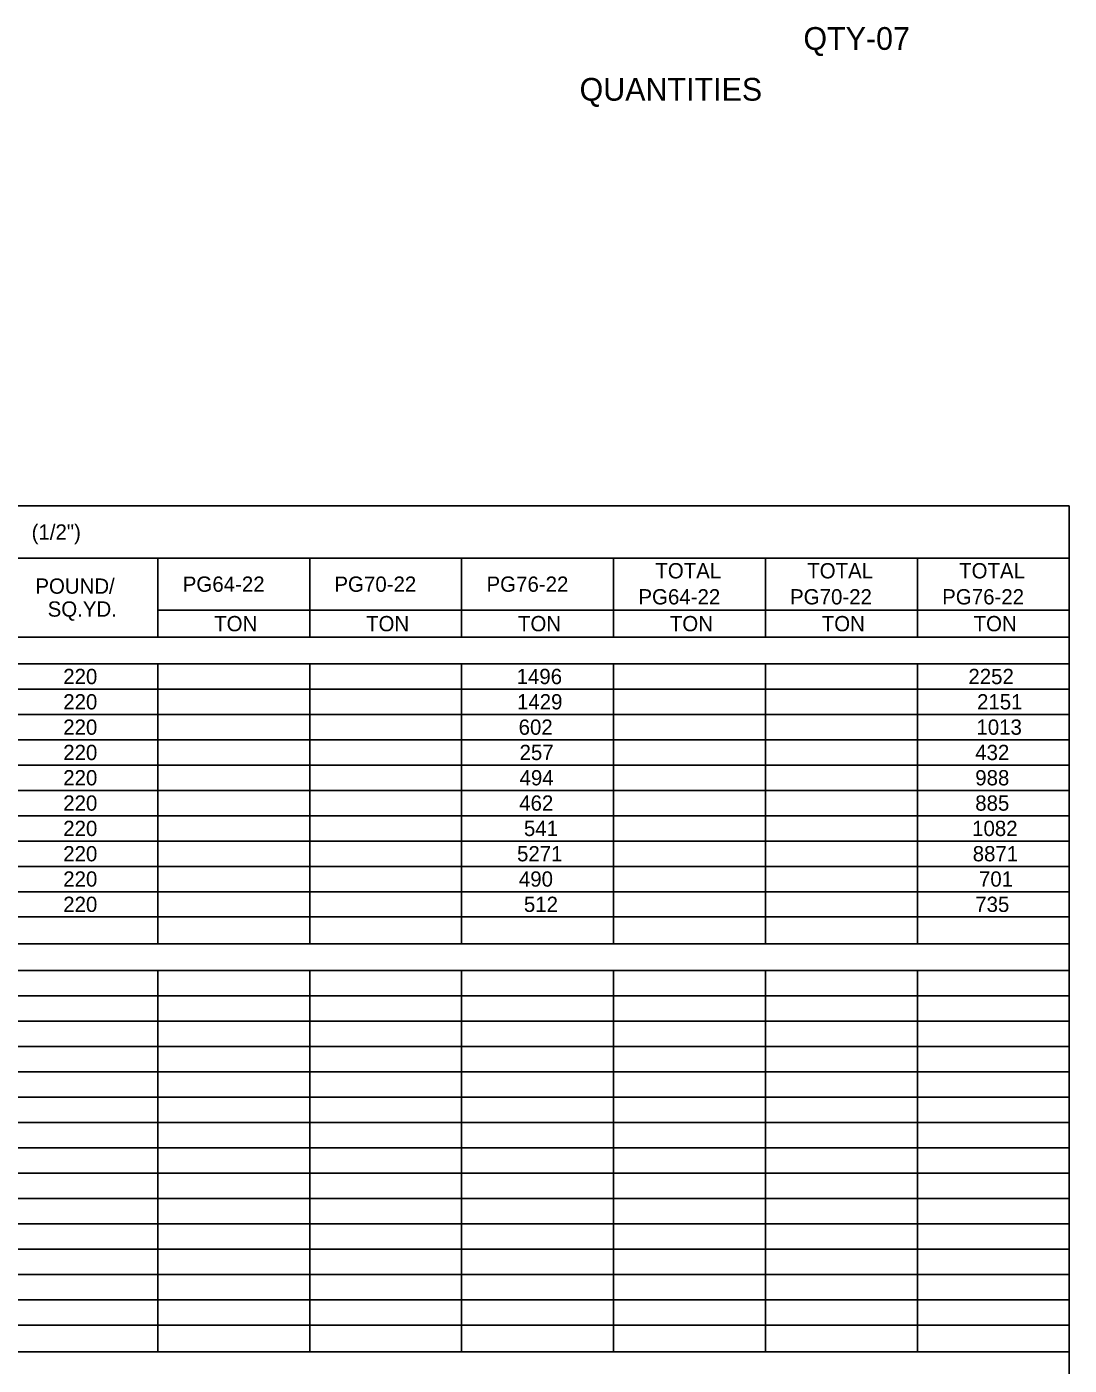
# Model space of a CAD drawing. Extents: x 1226590 to 1228573, y 151304 to 154224.
# Drawn here: x 1227882.1 to 1228150.7, y 151960.6 to 152305.5 of the extents above; entities that cross this region are included whole.
import ezdxf

# ---------------------------------------------------------------- set-up
doc = ezdxf.new("R2010")
doc.units = 0
doc.layers.add('R_Border', color=7, linetype='Continuous')
doc.layers.add('R_Dimension', color=7, linetype='Continuous')

msp = doc.modelspace()

# ---------------------------------------------------------------- linework, layer by layer
at = {"layer": 'R_Dimension'}
for p, q in [((1226590.27, 152182.03), (1228150.73, 152182.03)), ((1228150.73, 151484.92), (1228150.73, 152182.03)), ((1226898.37, 152168.6), (1228150.73, 152168.6)), ((1227915.91, 152148.27), (1227915.91, 152168.6)), ((1227955.05, 152148.27), (1227955.05, 152168.6)), ((1227994.18, 152148.27), (1227994.18, 152168.6)), ((1228033.32, 152148.27), (1228033.32, 152168.6)), ((1228072.46, 152148.27), (1228072.46, 152168.6)), ((1228111.59, 152148.27), (1228111.59, 152168.6)), ((1227915.91, 152155.17), (1228150.73, 152155.17)), ((1226590.27, 152148.27), (1228150.73, 152148.27)), ((1227837.64, 152148.27), (1228150.73, 152148.27)), ((1226590.27, 152141.36), (1228150.73, 152141.36)), ((1227915.91, 152069.23), (1227915.91, 152141.36)), ((1227955.05, 152069.23), (1227955.05, 152141.36)), ((1227994.18, 152069.23), (1227994.18, 152141.36)), ((1228033.32, 152069.23), (1228033.32, 152141.36)), ((1228072.46, 152069.23), (1228072.46, 152141.36)), ((1228111.59, 152069.23), (1228111.59, 152141.36)), ((1226590.27, 152134.84), (1228150.73, 152134.84)), ((1226590.27, 152128.31), (1228150.73, 152128.31)), ((1226590.27, 152121.79), (1228150.73, 152121.79)), ((1226590.27, 152115.27), (1228150.73, 152115.27)), ((1226590.27, 152108.75), (1228150.73, 152108.75)), ((1226590.27, 152102.22), (1228150.73, 152102.22)), ((1226590.27, 152095.7), (1228150.73, 152095.7)), ((1226590.27, 152089.18), (1228150.73, 152089.18)), ((1226590.27, 152082.65), (1228150.73, 152082.65)), ((1226590.27, 152076.13), (1228150.73, 152076.13)), ((1226590.27, 152069.23), (1228150.73, 152069.23)), ((1226590.27, 152062.32), (1228150.73, 152062.32)), ((1227915.91, 151964.1), (1227915.91, 152062.32)), ((1227955.05, 151964.1), (1227955.05, 152062.32)), ((1227994.18, 151964.1), (1227994.18, 152062.32)), ((1228033.32, 151964.1), (1228033.32, 152062.32)), ((1228072.46, 151964.1), (1228072.46, 152062.32)), ((1228111.59, 151964.1), (1228111.59, 152062.32)), ((1226590.27, 152055.8), (1228150.73, 152055.8)), ((1226590.27, 152049.27), (1228150.73, 152049.27)), ((1226590.27, 152042.75), (1228150.73, 152042.75)), ((1226590.27, 152036.23), (1228150.73, 152036.23)), ((1226590.27, 152029.71), (1228150.73, 152029.71)), ((1226590.27, 152023.18), (1228150.73, 152023.18)), ((1226590.27, 152016.66), (1228150.73, 152016.66)), ((1226590.27, 152010.14), (1228150.73, 152010.14)), ((1226590.27, 152003.61), (1228150.73, 152003.61)), ((1226590.27, 151997.09), (1228150.73, 151997.09)), ((1226590.27, 151990.57), (1228150.73, 151990.57)), ((1226590.27, 151984.05), (1228150.73, 151984.05)), ((1226590.27, 151977.52), (1228150.73, 151977.52)), ((1226590.27, 151971), (1228150.73, 151971)), ((1226590.27, 151964.1), (1228150.73, 151964.1))]:
    msp.add_line(p, q, dxfattribs=at)

# ---------------------------------------------------------------- texts
at = {"layer": 'R_Border'}
for s, height, p in [('QTY-07', 5.861, (1228082.24, 152299.55)), ('QUANTITIES', 5.862, (1228024.56, 152286.45))]:
    msp.add_text(s, height=height, dxfattribs=at).set_placement(p)
at = {"layer": 'R_Dimension'}
for s, p in [(' (1/2")', (1227881.92, 152173.35)), ('TOTAL', (1228044.09, 152163.37)), ('TOTAL', (1228083.22, 152163.37)), ('TOTAL', (1228122.36, 152163.37)), ('PG', (1227922.31, 152159.92)), (' 64-22', (1227928.48, 152159.92)), ('PG', (1227961.38, 152159.92)), (' 70-22', (1227967.55, 152159.92)), ('PG', (1228000.58, 152159.92)), (' 76-22', (1228006.75, 152159.92)), ('POUND', (1227884.34, 152159.42)), (' /', (1227901.84, 152159.42)), ('PG', (1228039.72, 152156.66)), (' 64-22', (1228045.88, 152156.66)), ('PG', (1228078.79, 152156.66)), (' 70-22', (1228084.96, 152156.66)), ('PG', (1228117.99, 152156.66)), (' 76-22', (1228124.16, 152156.66)), ('SQ.YD.', (1227887.51, 152153.51)), ('TON', (1227930.41, 152149.75)), ('TON', (1227969.55, 152149.75)), ('TON', (1228008.69, 152149.75)), ('TON', (1228047.82, 152149.75)), ('TON', (1228086.96, 152149.75)), ('TON', (1228126.09, 152149.75)), ('220', (1227891.52, 152136.13)), ('1496', (1228008.34, 152136.13)), ('2252', (1228124.75, 152136.13)), ('220', (1227891.52, 152129.61)), ('1429', (1228008.44, 152129.61)), ('2151', (1228126.98, 152129.61)), ('220', (1227891.52, 152123.08)), ('602', (1228008.86, 152123.08)), ('1013', (1228126.82, 152123.08)), ('220', (1227891.52, 152116.56)), ('257', (1228009.1, 152116.56)), ('432', (1228126.51, 152116.56)), ('220', (1227891.52, 152110.04)), ('494', (1228009.1, 152110.04)), ('988', (1228126.51, 152110.04)), ('220', (1227891.52, 152103.52)), ('462', (1228009.01, 152103.52)), ('885', (1228126.51, 152103.52)), ('220', (1227891.52, 152096.99)), ('541', (1228010.22, 152096.99)), ('1082', (1228125.71, 152096.99)), ('220', (1227891.52, 152090.47)), ('5271', (1228008.45, 152090.47)), ('8871', (1228125.86, 152090.47)), ('220', (1227891.52, 152083.95)), ('490', (1228008.93, 152083.95)), ('701', (1228127.47, 152083.95)), ('220', (1227891.52, 152077.43)), ('512', (1228010.22, 152077.43)), ('735', (1228126.51, 152077.43))]:
    msp.add_text(s, height=3.935, dxfattribs=at).set_placement(p)

doc.saveas('drawing.dxf')
